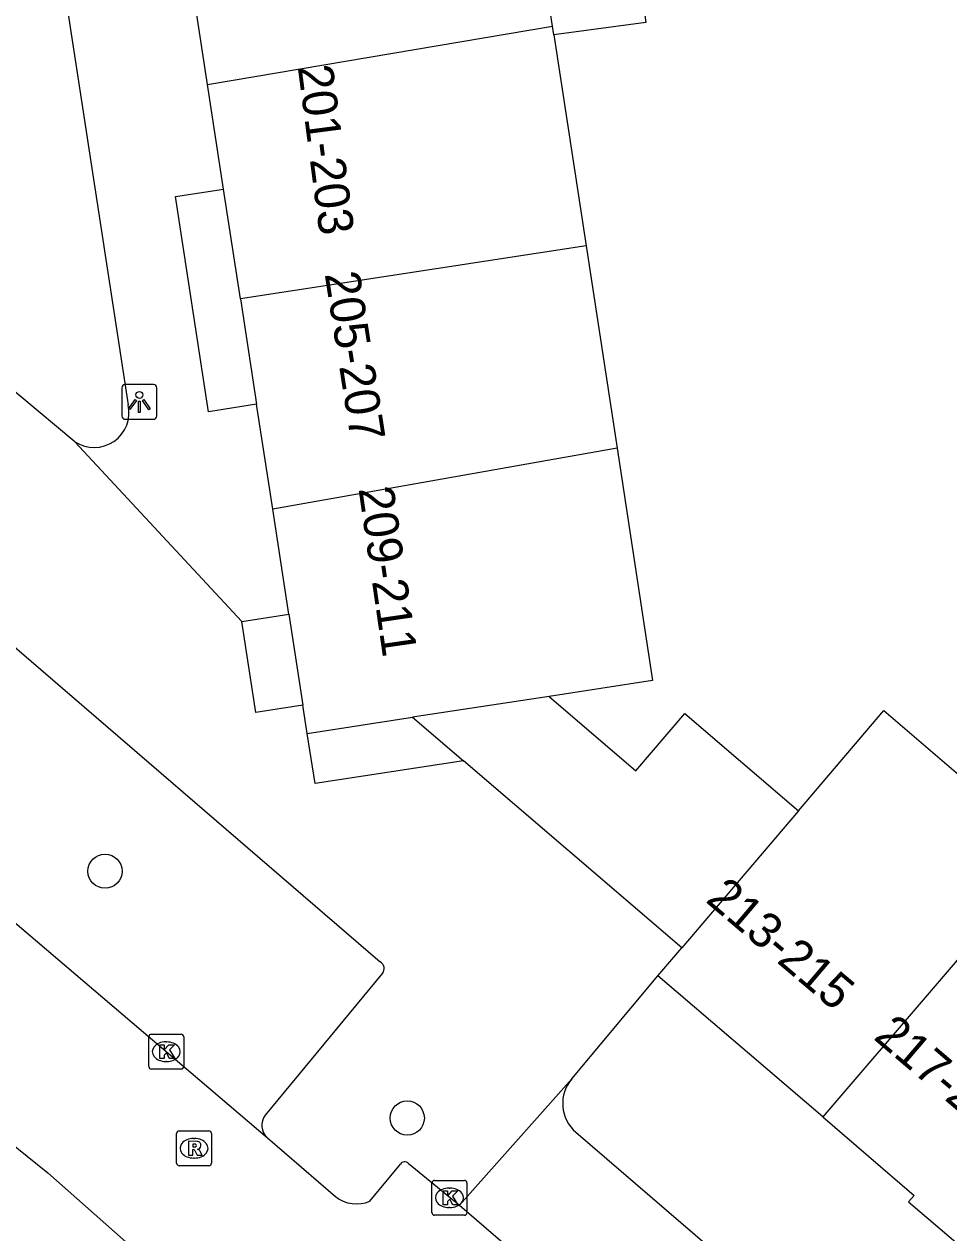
# Model space of a CAD drawing. Extents: x 159280 to 160375, y 384531 to 385872.
# Drawn here: x 159724.01 to 159750.49, y 384844.56 to 384879.19 of the extents above; entities that cross this region are included whole.
import ezdxf

# ---------------------------------------------------------------- set-up
doc = ezdxf.new("R2010")
doc.units = 0
for name, color, linetype in [('IMGEO_Boom', 7, 'Continuous'), ('IMGEO_Kolk', 7, 'Continuous'), ('IMGEO_Lichtpunt', 7, 'Continuous'), ('IMGEO_Pand', 7, 'Continuous'), ('IMGEO_Pand_nummerreeks', 7, 'Continuous'), ('IMGEO_Parkeervlak_open', 7, 'Continuous'), ('IMGEO_Rijbaan_lokaal_open', 7, 'Continuous'), ('IMGEO_Rioolput', 7, 'Continuous'), ('IMGEO_Voetpad_open', 7, 'Continuous')]:
    doc.layers.add(name, color=color, linetype=linetype)

msp = doc.modelspace()

# ---------------------------------------------------------------- linework, layer by layer
at = {"layer": 'IMGEO_Boom'}
for centre in [(159726.324, 384854.922), (159734.98, 384847.851)]:
    msp.add_circle(centre, 0.489, dxfattribs=at)
at = {"layer": 'IMGEO_Kolk'}
for p, q in [((159727.577, 384849.326), (159727.577, 384850.178)), ((159727.652, 384850.252), (159728.504, 384850.252)), ((159728.065, 384850.032), (159728.09, 384850.032)), ((159728.578, 384850.178), (159728.578, 384849.326)), ((159728.088, 384849.472), (159728.063, 384849.472)), ((159728.504, 384849.252), (159727.652, 384849.252)), ((159735.688, 384845.139), (159735.688, 384845.991)), ((159735.763, 384846.065), (159736.615, 384846.065)), ((159736.689, 384845.991), (159736.689, 384845.139)), ((159736.176, 384845.845), (159736.201, 384845.845)), ((159736.199, 384845.285), (159736.174, 384845.285)), ((159736.615, 384845.065), (159735.763, 384845.065))]:
    msp.add_line(p, q, dxfattribs=at)
for points in [[(159727.577, 384849.326), (159727.577, 384850.178)], [(159727.652, 384850.252), (159728.504, 384850.252)], [(159728.578, 384850.178), (159728.578, 384849.326)], [(159727.898, 384849.952), (159728.021, 384849.952), (159728.021, 384849.801), (159728.151, 384849.952), (159728.315, 384849.952), (159728.169, 384849.801), (159728.322, 384849.552), (159728.17, 384849.552), (159728.085, 384849.716), (159728.021, 384849.649), (159728.021, 384849.552), (159727.898, 384849.552), (159727.898, 384849.952)], [(159728.504, 384849.252), (159727.652, 384849.252)], [(159735.688, 384845.139), (159735.688, 384845.991)], [(159735.763, 384846.065), (159736.615, 384846.065)], [(159736.689, 384845.991), (159736.689, 384845.139)], [(159736.009, 384845.765), (159736.132, 384845.765), (159736.132, 384845.614), (159736.262, 384845.765), (159736.426, 384845.765), (159736.28, 384845.614), (159736.433, 384845.365), (159736.281, 384845.365), (159736.196, 384845.529), (159736.132, 384845.462), (159736.132, 384845.365), (159736.009, 384845.365), (159736.009, 384845.765)], [(159736.615, 384845.065), (159735.763, 384845.065)]]:
    msp.add_lwpolyline(points, dxfattribs=at)
for centre, start, end in [((159727.654, 384850.176), 91.552, 178.448), ((159727.654, 384850.176), 91.552, 178.448), ((159728.502, 384850.176), 1.552, 88.448), ((159728.502, 384850.176), 1.552, 88.448), ((159727.654, 384849.328), 181.552, 268.448), ((159727.654, 384849.328), 181.552, 268.448), ((159728.502, 384849.328), 271.552, 358.448), ((159728.502, 384849.328), 271.552, 358.448), ((159735.765, 384845.989), 91.552, 178.448), ((159735.765, 384845.989), 91.552, 178.448), ((159736.613, 384845.989), 1.552, 88.448), ((159736.613, 384845.989), 1.552, 88.448), ((159735.765, 384845.141), 181.552, 268.448), ((159735.765, 384845.141), 181.552, 268.448), ((159736.613, 384845.141), 271.552, 358.448), ((159736.613, 384845.141), 271.552, 358.448)]:
    msp.add_arc(centre, 0.0765, start, end, dxfattribs=at)
for centre, major_axis, ratio, start_param, end_param in [((159728.064, 384849.752), (-0.387, 0.002), 0.722429, 4.712389, 7.853982), ((159728.089, 384849.752), (-0.39, 0.002), 0.717154, 1.570796, 4.712389), ((159736.175, 384845.565), (-0.387, 0.002), 0.722429, 4.712389, 7.853982), ((159736.2, 384845.565), (-0.39, 0.002), 0.717154, 1.570796, 4.712389)]:
    msp.add_ellipse(centre, major_axis=major_axis, ratio=ratio, start_param=start_param, end_param=end_param, dxfattribs=at)
at = {"layer": 'IMGEO_Lichtpunt'}
for p, q in [((159726.809, 384868.772), (159726.809, 384867.965)), ((159726.809, 384868.772), (159726.809, 384867.965)), ((159727.711, 384868.867), (159726.903, 384868.867)), ((159727.711, 384868.867), (159726.903, 384868.867)), ((159727.805, 384867.965), (159727.805, 384868.772)), ((159727.805, 384867.965), (159727.805, 384868.772)), ((159726.903, 384867.871), (159727.711, 384867.871)), ((159726.903, 384867.871), (159727.711, 384867.871))]:
    msp.add_line(p, q, dxfattribs=at)
for points in [[(159727.183, 384868.436), (159727.222, 384868.408), (159727.034, 384868.146), (159726.996, 384868.173), (159727.183, 384868.436)], [(159727.285, 384868.388), (159727.332, 384868.388), (159727.332, 384868.066), (159727.285, 384868.066), (159727.285, 384868.388)], [(159727.395, 384868.408), (159727.433, 384868.435), (159727.62, 384868.173), (159727.581, 384868.145), (159727.395, 384868.408)]]:
    msp.add_lwpolyline(points, dxfattribs=at)
msp.add_circle((159727.308, 384868.57), 0.0994, dxfattribs=at)
for centre, start, end in [((159726.903, 384868.772), 90, 180), ((159726.903, 384868.772), 90, 180), ((159727.711, 384868.772), 0, 90), ((159727.711, 384868.772), 0, 90), ((159726.903, 384867.965), 180, 270), ((159726.903, 384867.965), 180, 270), ((159727.711, 384867.965), 270, 0), ((159727.711, 384867.965), 270, 360)]:
    msp.add_arc(centre, 0.0946, start, end, dxfattribs=at)
at = {"layer": 'IMGEO_Pand'}
for points in [[(159738.248, 384884.977), (159740.974, 384885.351), (159741.813, 384879.242), (159739.182, 384878.881)], [(159739.143, 384879.134), (159738.248, 384884.977)], [(159729.262, 384877.466), (159728.802, 384880.466)], [(159729.262, 384877.466), (159739.143, 384879.134)], [(159739.182, 384878.881), (159739.143, 384879.134)], [(159739.182, 384878.881), (159740.105, 384872.838)], [(159729.721, 384874.466), (159729.262, 384877.466)], [(159730.202, 384871.325), (159729.721, 384874.466)], [(159740.105, 384872.838), (159730.202, 384871.325)], [(159740.105, 384872.838), (159740.991, 384867.041)], [(159730.202, 384871.325), (159730.666, 384868.299)], [(159731.127, 384865.292), (159730.666, 384868.299)], [(159740.991, 384867.041), (159731.127, 384865.292)], [(159740.991, 384867.041), (159742.008, 384860.387), (159739.042, 384859.932)], [(159731.588, 384862.284), (159731.127, 384865.292)], [(159731.588, 384862.284), (159731.988, 384859.675)], [(159739.042, 384859.932), (159735.134, 384859.334)], [(159739.042, 384859.932), (159741.527, 384857.802), (159742.931, 384859.44), (159746.181, 384856.654)], [(159732.111, 384858.871), (159731.988, 384859.675)], [(159746.181, 384856.654), (159748.633, 384859.528), (159753.378, 384855.455)], [(159732.111, 384858.871), (159735.134, 384859.334)], [(159735.134, 384859.334), (159736.591, 384858.085)], [(159742.843, 384852.727), (159739.576, 384855.526), (159736.591, 384858.085)], [(159746.181, 384856.654), (159742.843, 384852.727)], [(159753.378, 384855.455), (159746.878, 384847.882)], [(159742.158, 384851.928), (159742.843, 384852.727)], [(159746.878, 384847.882), (159742.158, 384851.928)], [(159746.878, 384847.882), (159749.498, 384845.636), (159749.339, 384845.45), (159751.404, 384843.68), (159751.553, 384843.854), (159751.616, 384843.8)]]:
    msp.add_lwpolyline(points, dxfattribs=at)
at = {"layer": 'IMGEO_Parkeervlak_open'}
msp.add_lwpolyline([(159795.301, 384799.677), (159739.807, 384847.441)], dxfattribs=at)
msp.add_arc((159740.515, 384848.263), 1.084, 139.167, 229.2754, dxfattribs=at)
at = {"layer": 'IMGEO_Rijbaan_lokaal_open'}
for points in [[(159699.492, 384867.526), (159702.199, 384865.083), (159707.188, 384860.785), (159707.728, 384860.32), (159709.722, 384858.694), (159712.404, 384856.508), (159717.716, 384852.027), (159720.014, 384850.089), (159721.225, 384849.067), (159724.685, 384846.279), (159730.906, 384840.77), (159739.014, 384833.816), (159740.591, 384832.447), (159759.273, 384816.324), (159771.863, 384805.574), (159782.28, 384796.583), (159785.886, 384793.489), (159786.318, 384793.112)], [(159707.433, 384867.104), (159718.564, 384857.853), (159730.976, 384847.284)], [(159730.976, 384847.284), (159732.921, 384845.603)], [(159735.009, 384846.557), (159736.472, 384845.359)], [(159733.911, 384845.469), (159734.783, 384846.528)], [(159736.472, 384845.359), (159740.294, 384842.056), (159742.585, 384840.06), (159771.508, 384815.272), (159784.792, 384803.827), (159787.989, 384801.011), (159790.949, 384798.462)]]:
    msp.add_lwpolyline(points, dxfattribs=at)
for centre, radius, start, end in [((159734.908, 384846.45), 0.147, 46.6274, 147.9969), ((159733.529, 384846.369), 0.978, 231.5777, 293.0056)]:
    msp.add_arc(centre, radius, start, end, dxfattribs=at)
at = {"layer": 'IMGEO_Rioolput'}
for p, q in [((159728.373, 384846.558), (159728.373, 384847.41)), ((159728.448, 384847.484), (159729.3, 384847.484)), ((159728.861, 384847.264), (159728.886, 384847.264)), ((159729.374, 384847.41), (159729.374, 384846.558)), ((159728.884, 384846.704), (159728.859, 384846.704)), ((159729.3, 384846.484), (159728.448, 384846.484))]:
    msp.add_line(p, q, dxfattribs=at)
for points in [[(159728.373, 384846.558), (159728.373, 384847.41)], [(159728.448, 384847.484), (159729.3, 384847.484)], [(159729.374, 384847.41), (159729.374, 384846.558)], [(159728.962, 384847.182), (159728.71, 384847.184), (159728.71, 384846.784)], [(159728.71, 384846.784), (159728.834, 384846.784), (159728.834, 384846.946), (159728.845, 384846.946)], [(159728.888, 384847.103), (159728.834, 384847.103), (159728.834, 384847.022)], [(159728.834, 384847.022), (159728.886, 384847.022)], [(159728.892, 384846.917), (159728.963, 384846.784), (159729.103, 384846.784), (159729.038, 384846.91)], [(159729.3, 384846.484), (159728.448, 384846.484)]]:
    msp.add_lwpolyline(points, dxfattribs=at)
for centre, radius, start, end in [((159728.45, 384847.408), 0.0765, 91.552, 178.448), ((159728.45, 384847.408), 0.0765, 91.552, 178.448), ((159729.298, 384847.408), 0.0765, 1.552, 88.448), ((159729.298, 384847.408), 0.0765, 1.552, 88.448), ((159728.844, 384846.893), 0.0533, 26.0293, 88.6989), ((159728.87, 384847.211), 0.19, 274.7715, 282.9687), ((159728.894, 384847.007), 0.0964, 77.0061, 93.1865), ((159728.908, 384847.064), 0.0378, 276.6634, 79.6772), ((159728.961, 384847.072), 0.109, 350.3612, 89.416), ((159728.959, 384847.072), 0.112, 277.5842, 350.9817), ((159728.943, 384846.857), 0.108, 29.5134, 73.7905), ((159728.45, 384846.56), 0.0765, 181.552, 268.448), ((159728.45, 384846.56), 0.0765, 181.552, 268.448), ((159729.298, 384846.56), 0.0765, 271.552, 358.448), ((159729.298, 384846.56), 0.0765, 271.552, 358.448)]:
    msp.add_arc(centre, radius, start, end, dxfattribs=at)
for centre, major_axis, ratio, start_param, end_param in [((159728.86, 384846.984), (-0.387, 0.002), 0.722429, 4.712389, 7.853982), ((159728.885, 384846.984), (-0.39, 0.002), 0.717154, 1.570796, 4.712389)]:
    msp.add_ellipse(centre, major_axis=major_axis, ratio=ratio, start_param=start_param, end_param=end_param, dxfattribs=at)
at = {"layer": 'IMGEO_Voetpad_open'}
for points in [[(159724.158, 384886.7), (159726.988, 384868.282)], [(159730.666, 384868.299), (159729.284, 384868.087), (159728.338, 384874.254), (159729.721, 384874.466)], [(159725.46, 384867.229), (159721.77, 384870.297)], [(159730.244, 384862.078), (159725.46, 384867.229)], [(159730.244, 384862.078), (159731.588, 384862.284)], [(159731.988, 384859.675), (159730.644, 384859.469), (159730.244, 384862.078)], [(159723.238, 384861.769), (159734.206, 384852.326)], [(159736.591, 384858.085), (159732.339, 384857.432), (159732.111, 384858.871)], [(159734.272, 384851.997), (159730.915, 384847.936)], [(159739.694, 384848.972), (159742.158, 384851.928)], [(159739.694, 384848.972), (159736.472, 384845.359)]]:
    msp.add_lwpolyline(points, dxfattribs=at)
for centre, radius, start, end in [((159726.013, 384868.062), 1, 236.4481, 12.6962), ((159734.099, 384852.133), 0.22, 321.7208, 60.966), ((159731.291, 384847.642), 0.477, 142.0184, 228.6715)]:
    msp.add_arc(centre, radius, start, end, dxfattribs=at)

# ---------------------------------------------------------------- texts
at = {"layer": 'IMGEO_Pand_nummerreeks'}
for s, rotation, p in [('201-203', 277.454, (159731.842, 384877.969)), ('205-207', 278.915, (159732.613, 384872.035)), ('209-211', 278.2733, (159733.582, 384865.883)), ('213-215', 319.6351, (159743.494, 384854.063)), ('217-219', 319.5148, (159748.303, 384850.132))]:
    msp.add_text(s, height=1, rotation=rotation, dxfattribs=at).set_placement(p)

doc.saveas('drawing.dxf')
